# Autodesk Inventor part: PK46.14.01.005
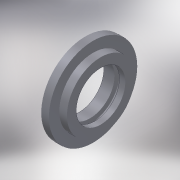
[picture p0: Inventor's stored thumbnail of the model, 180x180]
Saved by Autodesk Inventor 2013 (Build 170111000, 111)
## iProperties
Shininess: 64.0
Length Units: 11269
Angle Units: 11279
Time Units: 11290
Mass Units: 11283
Length Display Precision: 3
Angle Display Precision: 2
Compacted: True
Part Number: PK46.14.01.005
Document SubType Name: Modeling
Created: 2004-11
Material: Сталь высокопрочная низколегированная
Designer: ELarisa
Manufacturer: Standard
Standards Organization: Custom
Density: 7.84 g/cm^3
Density: 0.0
Volumn: 0.0
Area: 0.0
PropertySet Name: Model Information
Control State: 0
Master: False
Checked Out: False
Checked Out Date: 2008-10-15
Last Check In Date: 2008-10-15
Author: ELarisa
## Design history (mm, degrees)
sketch "Эскиз1"
  geometry: L1 (-19.32, -0.098)-(-19.32, 41.402); L2 (-19.32, 41.402)-(-11.32, 41.402); L3 (-11.32, 41.402)-(-11.32, 57.402); L4 (-11.32, 57.402)-(-1.32, 57.402); L5 (-1.32, 57.402)-(-1.32, 43.902); L6 (-1.32, 43.902)-(8.68, 43.902); L7 (8.68, 43.902)-(8.68, -0.098); L8 (8.68, -0.098)-(-19.32, -0.098); L9 (-19.32, 31.902)-(-5.32, 31.902); L10 (-5.32, 31.902)-(-5.32, 38.452); L11 (-5.32, 38.452)-(0.98, 38.452); L12 (0.98, 38.452)-(0.98, 31.902); L13 (0.98, 31.902)-(8.68, 31.902)
  constraints: 26 end point, 9 parallel, 3 perpendicular, 2 point on line, 1 collinear, 1 vertical
  dimensions: "d0" = 28 distance of L7.end L1.start; "d1" = 8 distance of L1.end L2.end; "d2" = 18 distance between parallel lines of L5 L1; "d3" = 6.3 distance of L10.end L11.end; "d4" = 14 distance between parallel lines of L7 L10; "d5" = 57.5 distance between parallel lines of L4 L8; "d6" = 41.5 distance between parallel lines of L2 L8; "d7" = 44 distance of L6.end L7.end; "d8" = 32 distance between parallel lines of L8 L13; "d9" = 38.55 distance between parallel lines of L11 L8
revolve "Вращение1" sketch "Эскиз1" stored, may be unused: angle "d10" = 90 deg
body "Solid1"
